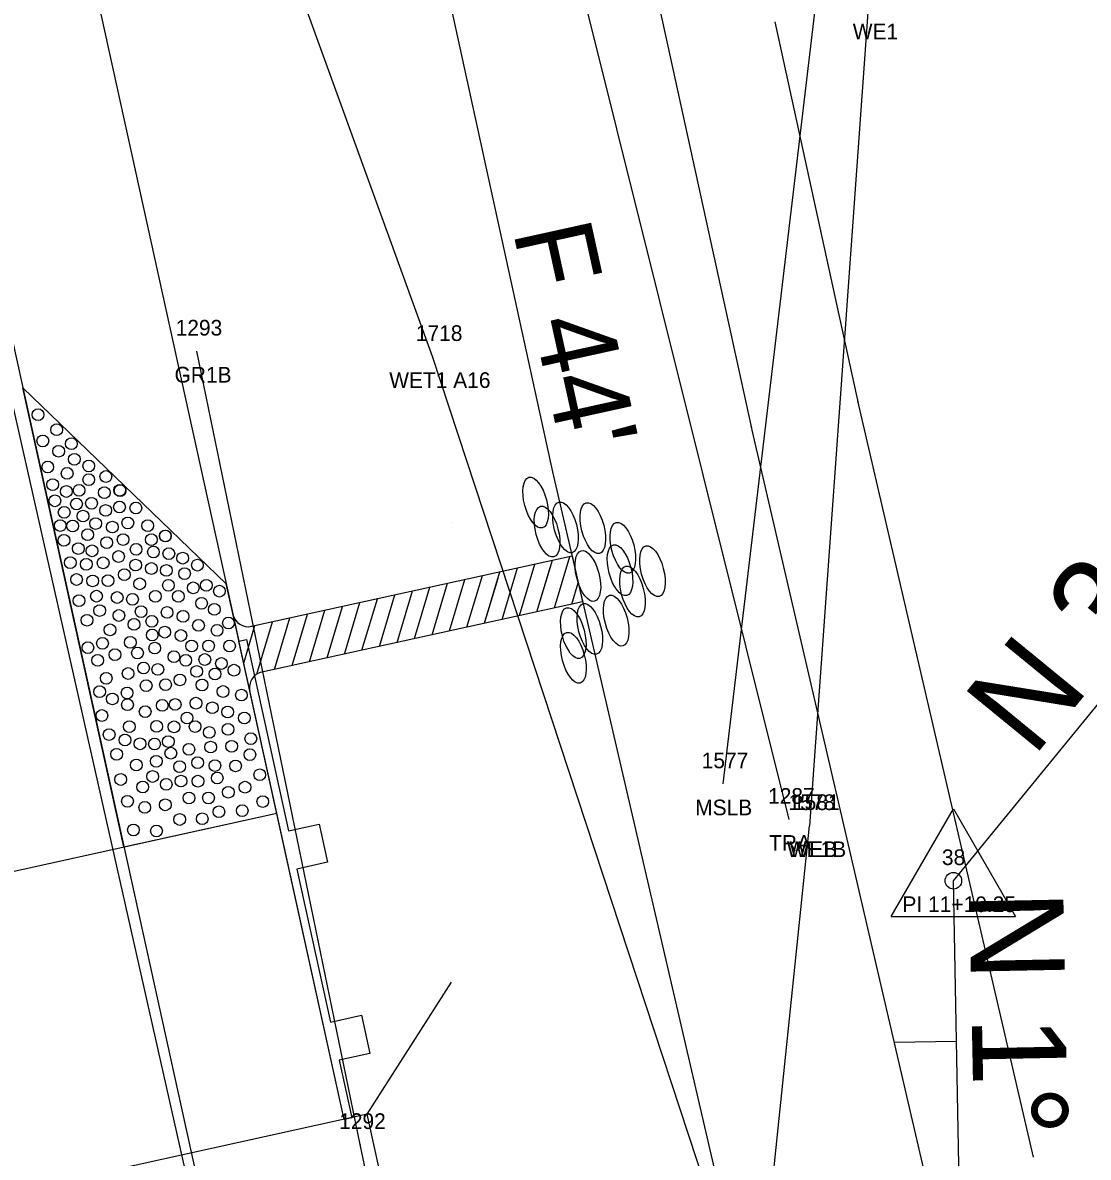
# Model space of a CAD drawing. Extents: x 2521558 to 2524785, y 882711 to 887632.
# Drawn here: x 2523776.7 to 2523844.7, y 885185.4 to 885257.9 of the extents above; entities that cross this region are included whole.
import ezdxf

# ---------------------------------------------------------------- set-up
doc = ezdxf.new("R2010")
doc.units = 0
for name, color, linetype in [('RD_EV_JW', 7, 'Continuous'), ('RD_EX_GuardRail', 7, 'Continuous'), ('RD_EX_GuardRail_txCode', 7, 'Continuous'), ('RD_EX_H2O', 7, 'Continuous'), ('RD_EX_H2O_txCode', 7, 'Continuous'), ('RD_EX_H2O_WetLd_txCode', 7, 'Continuous'), ('RD_EX_Misc', 7, 'Continuous'), ('RD_EX_Misc_txCode', 7, 'Continuous'), ('RD_EX_Road', 7, 'Continuous'), ('RD_EX_VEG', 7, 'Continuous'), ('RD_EX_VEG_txCode', 7, 'Continuous'), ('RD_HC_Cl', 7, 'Continuous'), ('RD_HC_Data', 7, 'Continuous'), ('RD_HC_Data_Tic', 7, 'Continuous'), ('RD_HC_txCode', 7, 'Continuous'), ('RD_PD_BCA', 7, 'Continuous'), ('RD_PD_Bridge', 7, 'Continuous'), ('RD_PD_CstnLmt', 7, 'Continuous'), ('RD_PD_DR_ErosCtrl', 7, 'Continuous'), ('RD_PD_Final_TrvlWay', 7, 'Continuous'), ('RD_PD_GR', 7, 'Continuous'), ('RD_PD_PaveShd', 7, 'Continuous'), ('RD_PD_TX_CstnLmt', 7, 'Continuous'), ('RD_SMD_Locator', 7, 'Continuous')]:
    doc.layers.add(name, color=color, linetype=linetype)

# ---------------------------------------------------------------- blocks, each defined once
blk = doc.blocks.new('TBC1')
at = {"layer": 'RD_PD_GR'}
blk.add_lwpolyline([(12.5, 2.5), (15, 2.5), (15, 0.492), (25, 0.492), (25, 2.5), (27.5, 2.5), (27.5, 0.492), (31.25, 0.492), (31.25, 0), (0, 0), (0, 0.492), (12.5, 0.492)], close=True, dxfattribs=at)

msp = doc.modelspace()

# ---------------------------------------------------------------- linework, layer by layer
at = {"layer": 'RD_EV_JW'}
msp.add_lwpolyline([(2523761.167, 885134.03), (2523808.209, 885149.207), (2523821.914, 885178.637), (2523802.851, 885236.548), (2523777.81, 885305.562), (2523748.196, 885444.322), (2523730.68, 885516.876), (2523708.637, 885617.3), (2523698.714, 885662.019), (2523727.827, 885665.815), (2523757.297, 885671.751)], dxfattribs=at)
at = {"layer": 'RD_EX_GuardRail'}
msp.add_lwpolyline([(2523803.786, 885159.912), (2523798.239, 885186.256), (2523787.795, 885236.892)], dxfattribs=at)
at = {"layer": 'RD_EX_H2O'}
for points in [[(2524064.856, 885165.15), (2524036.37, 885213.784), (2524057.223, 885252.722), (2524031.954, 885291.634), (2523983.255, 885326.297), (2523940.609, 885311.826), (2523904.837, 885305.013), (2523874.983, 885272.096), (2523850.319, 885280.241), (2523830.665, 885258.799), (2523826.928, 885206.612)], [(2523738.909, 885147.498), (2523743.695, 885138.843), (2523816.359, 885152.29), (2523822.427, 885163.299), (2523826.928, 885206.612)]]:
    msp.add_lwpolyline(points, dxfattribs=at)
at = {"layer": 'RD_EX_Misc'}
msp.add_lwpolyline([(2524066.305, 885165.351), (2524037.301, 885214.147), (2524057.946, 885253.065), (2524039.523, 885283.168), (2524032.922, 885292.565), (2523983.53, 885327.977), (2523940.238, 885313.274), (2523904.134, 885306.246), (2523874.86, 885272.666), (2523849.958, 885282.507), (2523827.651, 885261.934), (2523821.385, 885209.277)], dxfattribs=at)
at = {"layer": 'RD_EX_Road'}
msp.add_line((2523792.777, 885159.311), (2523771.239, 885254.787), dxfattribs=at)
at = {"layer": 'RD_EX_VEG'}
msp.add_lwpolyline([(2523825.623, 885207.01), (2523811.867, 885262.105), (2523733.022, 885654.224), (2523687.107, 885876.236)], dxfattribs=at)
at = {"layer": 'RD_HC_Cl'}
for p, q in [((2523836.106, 885203.1), (2523883.663, 885261.233)), ((2523837.18, 885148.323), (2523836.106, 885203.1))]:
    msp.add_line(p, q, dxfattribs=at)
at = {"layer": 'RD_HC_Data'}
for p, q in [((2523832.135, 885200.807), (2523836.107, 885207.686)), ((2523836.107, 885207.686), (2523840.076, 885200.807)), ((2523832.135, 885200.807), (2523840.076, 885200.807))]:
    msp.add_line(p, q, dxfattribs=at)
msp.add_circle((2523836.106, 885203.1), 0.529, dxfattribs=at)
at = {"layer": 'RD_HC_Data_Tic'}
msp.add_line((2523836.307, 885192.845), (2523832.308, 885192.766), dxfattribs=at)
at = {"layer": 'RD_PD_BCA'}
for p, q in [((2523824.701, 885257.92), (2523830.049, 885233.47)), ((2523829.993, 885233.72), (2523841.201, 885185.449))]:
    msp.add_line(p, q, dxfattribs=at)
at = {"layer": 'RD_PD_Bridge'}
for p, q in [((2523749.936, 885197.941), (2523792.907, 885207.403)), ((2523797.208, 885187.871), (2523792.907, 885207.403)), ((2523798.673, 885188.194), (2523804.058, 885196.62))]:
    msp.add_line(p, q, dxfattribs=at)
for points in [[(2523798.673, 885188.194), (2523752.772, 885178.086)], [(2523826.629, 885061.235), (2523798.673, 885188.194)]]:
    msp.add_lwpolyline(points, dxfattribs=at)
at = {"layer": 'RD_PD_CstnLmt'}
for p, q in [((2523789.142, 885326.887), (2523810.511, 885229.196)), ((2523810.511, 885229.196), (2523821.719, 885180.926))]:
    msp.add_line(p, q, dxfattribs=at)
at = {"layer": 'RD_PD_DR_ErosCtrl'}
for p, q in [((2523801.841, 885329.665), (2523823.211, 885231.974)), ((2523823.174, 885232.137), (2523834.383, 885183.866))]:
    msp.add_line(p, q, dxfattribs=at)
at = {"layer": 'RD_PD_Final_TrvlWay'}
msp.add_line((2523741.744, 885393.246), (2524015.933, 884148.078), dxfattribs=at)
at = {"layer": 'RD_PD_GR'}
msp.add_line((2523742.101, 885438.126), (2523790.488, 885218.39), dxfattribs=at)
at = {"layer": 'RD_PD_PaveShd'}
for p, q in [((2523776.689, 885234.551), (2523789.681, 885222.052)), ((2523783.141, 885205.253), (2523776.689, 885234.551)), ((2523791.303, 885219.337), (2523811.757, 885223.83)), ((2523810.638, 885220.513), (2523811.622, 885223.8)), ((2523810.638, 885220.513), (2523811.622, 885223.8)), ((2523811.757, 885223.83), (2523812.436, 885220.907)), ((2523807.287, 885219.776), (2523808.271, 885223.064)), ((2523807.287, 885219.776), (2523808.271, 885223.064)), ((2523808.404, 885220.022), (2523809.388, 885223.309)), ((2523808.404, 885220.022), (2523809.388, 885223.309)), ((2523809.521, 885220.267), (2523810.505, 885223.555)), ((2523809.521, 885220.267), (2523810.384, 885223.15)), ((2523803.935, 885219.04), (2523804.919, 885222.328)), ((2523803.935, 885219.04), (2523804.919, 885222.328)), ((2523805.052, 885219.286), (2523806.036, 885222.573)), ((2523805.052, 885219.286), (2523806.036, 885222.573)), ((2523806.169, 885219.531), (2523807.153, 885222.819)), ((2523806.169, 885219.531), (2523807.032, 885222.413)), ((2523790.326, 885219.122), (2523789.681, 885222.052)), ((2523800.583, 885218.304), (2523801.567, 885221.591)), ((2523800.583, 885218.304), (2523801.567, 885221.591)), ((2523801.7, 885218.549), (2523802.684, 885221.837)), ((2523801.7, 885218.549), (2523802.684, 885221.837)), ((2523802.818, 885218.795), (2523803.801, 885222.082)), ((2523802.818, 885218.795), (2523803.801, 885222.082)), ((2523811.756, 885220.758), (2523812.158, 885222.103)), ((2523811.756, 885220.758), (2523812.158, 885222.103)), ((2523812.436, 885220.907), (2523791.949, 885216.407)), ((2523797.231, 885217.568), (2523798.215, 885220.855)), ((2523797.231, 885217.568), (2523798.215, 885220.855)), ((2523798.348, 885217.813), (2523799.332, 885221.101)), ((2523798.348, 885217.813), (2523799.332, 885221.101)), ((2523799.466, 885218.058), (2523800.45, 885221.346)), ((2523799.466, 885218.058), (2523800.45, 885221.346)), ((2523793.879, 885216.831), (2523794.863, 885220.119)), ((2523793.879, 885216.831), (2523794.863, 885220.119)), ((2523794.997, 885217.077), (2523795.981, 885220.364)), ((2523794.997, 885217.077), (2523795.981, 885220.364)), ((2523796.114, 885217.322), (2523797.098, 885220.61)), ((2523790.796, 885216.992), (2523791.511, 885219.383)), ((2523791.625, 885216.273), (2523792.629, 885219.628)), ((2523792.762, 885216.586), (2523793.746, 885219.874)), ((2523792.762, 885216.586), (2523793.746, 885219.874)), ((2523790.971, 885216.193), (2523790.326, 885219.122)), ((2523792.907, 885207.403), (2523790.971, 885216.193)), ((2523783.141, 885205.253), (2523792.907, 885207.403))]:
    msp.add_line(p, q, dxfattribs=at)
for centre in [(2523777.666, 885232.841), (2523778.856, 885231.882), (2523778.856, 885231.882), (2523777.968, 885231.167), (2523777.968, 885231.167), (2523778.977, 885230.511), (2523778.977, 885230.511), (2523779.793, 885230.988), (2523779.793, 885230.988), (2523779.981, 885229.998), (2523779.981, 885229.998), (2523778.285, 885229.502), (2523778.285, 885229.502), (2523779.522, 885229.096), (2523779.522, 885229.096), (2523780.904, 885229.572), (2523778.599, 885228.38), (2523778.599, 885228.38), (2523780.902, 885228.695), (2523780.902, 885228.695), (2523781.994, 885228.895), (2523781.994, 885228.895), (2523779.472, 885227.942), (2523779.472, 885227.942), (2523780.286, 885228.017), (2523780.286, 885228.017), (2523781.895, 885227.867), (2523781.895, 885227.867), (2523782.878, 885228.022), (2523782.902, 885227.998), (2523778.738, 885227.346), (2523778.738, 885227.346), (2523780.119, 885227.145), (2523780.119, 885227.145), (2523781.078, 885227.19), (2523781.078, 885227.19), (2523782.865, 885226.95), (2523782.865, 885226.95), (2523783.909, 885226.886), (2523783.909, 885226.886), (2523779.333, 885226.612), (2523779.333, 885226.612), (2523780.537, 885226.371), (2523780.537, 885226.371), (2523781.98, 885226.731), (2523781.98, 885226.731), (2523779.08, 885225.767), (2523779.08, 885225.767), (2523779.876, 885225.741), (2523779.876, 885225.741), (2523781.34, 885225.894), (2523781.34, 885225.894), (2523782.41, 885225.668), (2523782.41, 885225.668), (2523783.396, 885225.935), (2523783.396, 885225.935), (2523784.667, 885225.761), (2523784.667, 885225.761), (2523779.317, 885224.822), (2523779.317, 885224.822), (2523780.831, 885225.184), (2523780.831, 885225.184), (2523783.094, 885224.873), (2523783.094, 885224.873), (2523784.896, 885224.866), (2523784.896, 885224.866), (2523785.786, 885225.108), (2523785.797, 885225.105), (2523780.235, 885224.299), (2523780.235, 885224.299), (2523781.114, 885224.154), (2523781.114, 885224.154), (2523782.05, 885224.678), (2523782.05, 885224.678), (2523783.924, 885224.247), (2523783.924, 885224.247), (2523785.033, 885224.081), (2523785.033, 885224.081), (2523779.722, 885223.401), (2523779.722, 885223.401), (2523780.743, 885223.296), (2523780.743, 885223.296), (2523781.821, 885223.387), (2523781.821, 885223.387), (2523782.805, 885223.79), (2523782.805, 885223.79), (2523786.014, 885223.973), (2523786.014, 885223.973), (2523786.9, 885223.688), (2523786.9, 885223.688), (2523783.172, 885222.632), (2523783.172, 885222.632), (2523783.893, 885223.243), (2523783.893, 885223.243), (2523784.902, 885223.024), (2523784.902, 885223.024), (2523785.859, 885222.903), (2523785.859, 885222.903), (2523787.018, 885222.701), (2523787.018, 885222.701), (2523787.841, 885223.241), (2523787.841, 885223.241), (2523780.123, 885222.324), (2523780.123, 885222.324), (2523781.15, 885222.234), (2523781.15, 885222.234), (2523782.128, 885222.251), (2523782.128, 885222.251), (2523784.155, 885222.048), (2523784.155, 885222.048), (2523785.988, 885221.955), (2523785.988, 885221.955), (2523788.407, 885221.955), (2523788.407, 885221.955), (2523781.397, 885221.261), (2523781.397, 885221.261), (2523782.715, 885221.176), (2523782.715, 885221.176), (2523785.157, 885221.252), (2523785.157, 885221.252), (2523786.624, 885221.248), (2523786.624, 885221.248), (2523787.572, 885221.791), (2523787.572, 885221.791), (2523789.246, 885221.58), (2523789.246, 885221.58), (2523789.246, 885221.58), (2523780.277, 885220.975), (2523780.277, 885220.975), (2523783.693, 885221.06), (2523783.693, 885221.06), (2523788.104, 885220.805), (2523788.104, 885220.805), (2523788.918, 885220.417), (2523788.918, 885220.417), (2523780.792, 885219.725), (2523780.792, 885219.725), (2523781.597, 885220.343), (2523781.597, 885220.343), (2523782.826, 885220.027), (2523782.826, 885220.027), (2523784.244, 885220.275), (2523784.244, 885220.275), (2523784.927, 885219.657), (2523784.927, 885219.657), (2523785.903, 885220.223), (2523785.903, 885220.223), (2523786.923, 885219.97), (2523786.923, 885219.97), (2523782.262, 885219.11), (2523782.262, 885219.11), (2523783.793, 885219.459), (2523783.793, 885219.459), (2523785.754, 885218.965), (2523785.754, 885218.965), (2523787.909, 885219.396), (2523787.909, 885219.396), (2523789.097, 885219.082), (2523789.097, 885219.082), (2523789.821, 885219.548), (2523789.821, 885219.548), (2523781.777, 885218.252), (2523781.777, 885218.252), (2523783.552, 885218.311), (2523783.552, 885218.311), (2523784.954, 885218.78), (2523784.954, 885218.78), (2523786.785, 885218.75), (2523786.785, 885218.75), (2523780.846, 885217.973), (2523780.846, 885217.973), (2523782.574, 885217.528), (2523782.574, 885217.528), (2523784.012, 885217.636), (2523784.012, 885217.636), (2523785.118, 885217.946), (2523785.118, 885217.946), (2523787.474, 885218.079), (2523787.474, 885218.079), (2523788.551, 885218.087), (2523788.551, 885218.087), (2523789.893, 885218.079), (2523789.893, 885218.079), (2523781.472, 885217.165), (2523781.472, 885217.165), (2523786.338, 885217.395), (2523786.338, 885217.395), (2523787.097, 885217.168), (2523787.097, 885217.168), (2523788.312, 885217.218), (2523788.312, 885217.218), (2523789.373, 885216.963), (2523789.373, 885216.963), (2523782.019, 885216.02), (2523782.019, 885216.02), (2523783.413, 885216.326), (2523783.413, 885216.326), (2523784.4, 885216.674), (2523784.4, 885216.674), (2523785.31, 885216.586), (2523785.31, 885216.586), (2523787.793, 885216.457), (2523787.793, 885216.457), (2523788.963, 885216.293), (2523788.963, 885216.293), (2523790.175, 885216.537), (2523790.175, 885216.537), (2523784.565, 885215.548), (2523784.565, 885215.548), (2523785.804, 885215.611), (2523785.804, 885215.611), (2523786.722, 885215.916), (2523786.722, 885215.916), (2523788.136, 885215.596), (2523788.136, 885215.596), (2523781.595, 885215.164), (2523782.41, 885214.704), (2523782.41, 885214.704), (2523783.351, 885215.084), (2523783.351, 885215.084), (2523789.478, 885215.174), (2523789.478, 885215.174), (2523790.65, 885214.948), (2523790.65, 885214.948), (2523783.374, 885214.333), (2523783.374, 885214.333), (2523784.503, 885213.892), (2523784.503, 885213.892), (2523785.594, 885214.289), (2523785.594, 885214.289), (2523786.419, 885214.352), (2523786.419, 885214.352), (2523787.746, 885214.431), (2523787.746, 885214.431), (2523788.795, 885214.138), (2523788.795, 885214.138), (2523789.769, 885213.867), (2523789.769, 885213.867), (2523781.741, 885213.643), (2523781.741, 885213.643), (2523787.173, 885213.486), (2523787.173, 885213.486), (2523790.833, 885213.487), (2523790.833, 885213.487), (2523782.204, 885212.429), (2523782.204, 885212.429), (2523783.492, 885212.933), (2523783.492, 885212.933), (2523785.234, 885212.949), (2523785.234, 885212.949), (2523786.348, 885212.919), (2523786.348, 885212.919), (2523787.691, 885212.938), (2523787.691, 885212.938), (2523788.593, 885212.565), (2523788.593, 885212.565), (2523789.79, 885212.765), (2523789.79, 885212.765), (2523783.214, 885212.079), (2523783.214, 885212.079), (2523784.178, 885211.839), (2523784.178, 885211.839), (2523785.102, 885211.825), (2523785.102, 885211.825), (2523785.978, 885211.982), (2523785.978, 885211.982), (2523790.024, 885211.682), (2523790.024, 885211.682), (2523791.249, 885212.164), (2523791.249, 885212.164), (2523782.68, 885211.17), (2523782.68, 885211.17), (2523786.142, 885211.239), (2523787.297, 885211.485), (2523787.297, 885211.485), (2523788.684, 885211.628), (2523788.684, 885211.628), (2523791.192, 885211.147), (2523791.192, 885211.147), (2523783.942, 885210.483), (2523783.942, 885210.483), (2523785.213, 885210.723), (2523785.213, 885210.723), (2523786.703, 885210.381), (2523786.703, 885210.381), (2523787.851, 885210.633), (2523787.851, 885210.633), (2523788.957, 885210.451), (2523788.957, 885210.451), (2523790.274, 885210.429), (2523790.274, 885210.429), (2523782.943, 885209.562), (2523782.943, 885209.562), (2523784.978, 885209.753), (2523784.978, 885209.753), (2523789.105, 885209.656), (2523789.105, 885209.656), (2523791.821, 885209.863), (2523791.821, 885209.863), (2523784.349, 885209.079), (2523784.349, 885209.079), (2523785.848, 885209.251), (2523785.848, 885209.251), (2523786.792, 885209.459), (2523786.792, 885209.459), (2523787.872, 885209.452), (2523787.872, 885209.452), (2523790.88, 885209.07), (2523790.88, 885209.07), (2523783.374, 885208.172), (2523783.374, 885208.172), (2523787.304, 885208.382), (2523787.304, 885208.382), (2523788.545, 885208.383), (2523788.545, 885208.383), (2523789.812, 885208.748), (2523789.812, 885208.748), (2523792.011, 885208.152), (2523792.011, 885208.152), (2523792.011, 885208.152), (2523784.477, 885207.78), (2523784.477, 885207.78), (2523785.788, 885207.946), (2523785.788, 885207.946), (2523789.211, 885207.501), (2523789.211, 885207.501), (2523790.7, 885207.573), (2523790.7, 885207.573), (2523786.707, 885207.01), (2523786.707, 885207.01), (2523788.147, 885207.055), (2523788.147, 885207.055), (2523783.756, 885206.341), (2523783.756, 885206.341), (2523785.225, 885206.274), (2523785.225, 885206.274)]:
    msp.add_circle(centre, 0.375, dxfattribs=at)
for centre, start, end in [((2523791.088, 885220.314), 192.41848, 282.38886), ((2523792.163, 885215.431), 102.38886, 192.41848)]:
    msp.add_arc(centre, 1, start, end, dxfattribs=at)
for centre in [(2523809.435, 885227.232), (2523811.34, 885225.65), (2523811.34, 885225.65), (2523813.084, 885225.604), (2523813.084, 885225.604), (2523810.164, 885225.383), (2523815.003, 885224.349), (2523815.003, 885224.349), (2523814.822, 885222.914), (2523814.822, 885222.914), (2523816.892, 885222.854), (2523816.892, 885222.854), (2523812.773, 885222.548), (2523812.773, 885222.548), (2523815.615, 885221.56), (2523815.615, 885221.56), (2523812.892, 885219.169), (2523812.892, 885219.169), (2523814.581, 885219.698), (2523814.581, 885219.698), (2523811.838, 885218.904), (2523811.838, 885218.904), (2523811.845, 885217.332), (2523811.845, 885217.332)]:
    msp.add_ellipse(centre, major_axis=(-0.426, 1.616), ratio=0.429445, dxfattribs=at)
at = {"layer": 'RD_SMD_Locator'}
for centre in [(2523787.795, 885236.892), (2523802.851, 885236.548), (2523804.069, 885225.964), (2523821.385, 885209.277), (2523825.623, 885207.01), (2523826.928, 885206.612), (2523826.928, 885206.612), (2523836.106, 885203.1), (2523798.239, 885186.256)]:
    msp.add_circle(centre, 0.001, dxfattribs=at)

# ---------------------------------------------------------------- block references
at = {"layer": 'RD_PD_Bridge', "rotation": -77.58151740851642}
msp.add_blockref('TBC1', (2523790.488, 885218.39), dxfattribs=at)

# ---------------------------------------------------------------- texts
at = {"layer": 'RD_EX_GuardRail_txCode'}
for s, p in [('1293', (2523786.449, 885237.892)), ('GR1B', (2523786.378, 885234.892)), ('1292', (2523796.892, 885187.256))]:
    msp.add_text(s, height=1, dxfattribs=at).set_placement(p)
at = {"layer": 'RD_EX_H2O_txCode'}
for s, p in [('WE1', (2523829.681, 885256.799)), ('1578', (2523825.582, 885207.612)), ('1581', (2523825.865, 885207.612)), ('WE1B', (2523825.471, 885204.612)), ('WEB', (2523825.637, 885204.612))]:
    msp.add_text(s, height=1, dxfattribs=at).set_placement(p)
at = {"layer": 'RD_EX_H2O_WetLd_txCode'}
for s, p in [('1718', (2523801.788, 885237.548)), ('WET1 A16', (2523800.087, 885234.548))]:
    msp.add_text(s, height=1, dxfattribs=at).set_placement(p)
at = {"layer": 'RD_EX_Misc_txCode'}
for s, p in [('1577', (2523820.038, 885210.277)), ('MSLB', (2523819.621, 885207.277))]:
    msp.add_text(s, height=1, dxfattribs=at).set_placement(p)
at = {"layer": 'RD_EX_VEG_txCode'}
for s, p in [('1287', (2523824.276, 885208.01)), ('TRA', (2523824.339, 885205.01))]:
    msp.add_text(s, height=1, dxfattribs=at).set_placement(p)
at = {"layer": 'RD_HC_Data'}
for s, rotation, p in [('N 39%%d 17\' 08" E', 50.71443, (2523841.195, 885210.9)), ('N 1%%d 07\' 21" W', 271.12261, (2523837.119, 885202.44))]:
    msp.add_text(s, height=6, rotation=rotation, dxfattribs=at).set_placement(p)
at = {"layer": 'RD_HC_txCode'}
for s, p in [('38', (2523835.374, 885204.1)), ('PI 11+10.25', (2523832.854, 885201.1))]:
    msp.add_text(s, height=1, dxfattribs=at).set_placement(p)
at = {"layer": 'RD_PD_TX_CstnLmt'}
msp.add_text("F 44'", height=5, rotation=282.41848, dxfattribs=at).set_placement((2523807.977, 885244.555))

doc.saveas('drawing.dxf')
